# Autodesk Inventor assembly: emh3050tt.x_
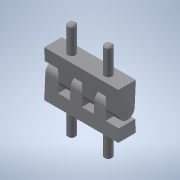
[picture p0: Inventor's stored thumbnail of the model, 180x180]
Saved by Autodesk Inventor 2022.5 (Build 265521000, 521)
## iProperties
Part Number: emh3050tt.x_
Material: 一般
Document SubType Name: Assembly
Designer: ImaoCorp
Sending System: SOLIDWORKS 2017-2017317
MC: AMD64
MC_MODEL: Intel64 Family 6 Model 60 Stepping 3, GenuineIntel
OS: Windows_NT
FRU: Parasolid Version 29.0, build 201,  4-17-2017
FORMAT: text
GUISE: transmit
KEY: emh3050tt
FILE: emh3050tt.x_t
DATE: Mon May 13 14:20:31 2019
Author: ImaoCorp
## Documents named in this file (4)
- X:\14_SW2022-Inv2022\00_全2023-1023新製品(TCC)まで\e\emh3050tt\EMH3050TT.iam
- X:\14_SW2022-Inv2022\00_全2023-1023新製品(TCC)まで\e\emh3050tt\emh3050tt_01.ipt
- X:\14_SW2022-Inv2022\00_全2023-1023新製品(TCC)まで\e\emh3050tt\emh3050tt_02.ipt
- X:\14_SW2022-Inv2022\00_全2023-1023新製品(TCC)まで\e\emh3050tt\emh3050tt_03.ipt
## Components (3 placed, 3 different names)
1. emh3050tt_01
2. emh3050tt_02
3. emh3050tt_03
